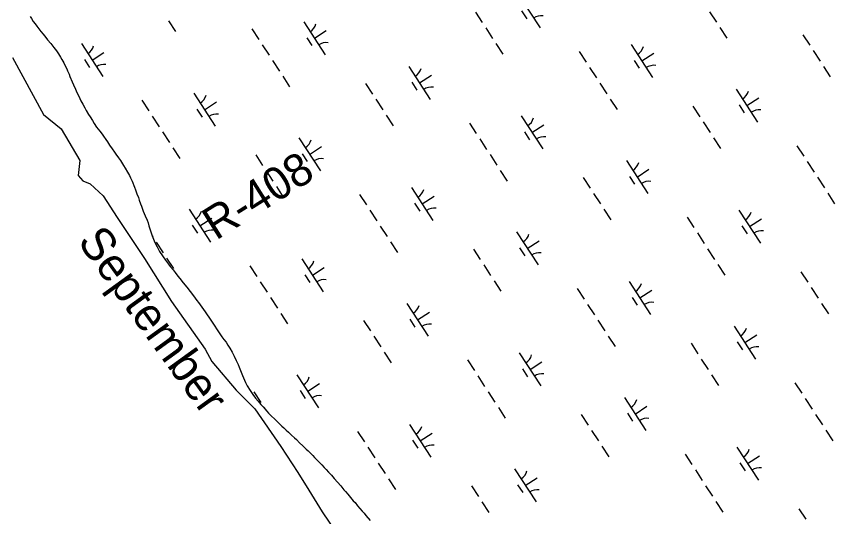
# Model space of a CAD drawing. Extents: x 3953924 to 3974542, y 193747 to 216192.
# Drawn here: x 3964702 to 3965741, y 203866 to 204501 of the extents above; entities that cross this region are included whole.
import ezdxf

# ---------------------------------------------------------------- set-up
doc = ezdxf.new("R2010")
doc.units = 0
for name, color, linetype in [('V-RIVR-EDGE', 7, 'Continuous'), ('V-RIVR-IDEN', 7, 'Continuous'), ('V-RIVR-RANG-IDEN', 7, 'Continuous'), ('V-WETL-SWMP', 7, 'Continuous')]:
    doc.layers.add(name, color=color, linetype=linetype)

msp = doc.modelspace()

# ---------------------------------------------------------------- linework, layer by layer
at = {"layer": 'V-RIVR-EDGE'}
msp.add_lwpolyline([(3964697.2, 204448.9), (3964736.3, 204376.5), (3964758.9, 204358.6), (3964782.7, 204318.3), (3964780.3, 204299.3), (3964786.2, 204292.2), (3964795.7, 204288.6), (3964812.3, 204273.2), (3964830.1, 204245.9), (3964864.6, 204193.6), (3964899, 204139), (3964941.7, 204078.5), (3964950, 204063), (3964980.9, 204026.2), (3965004.7, 204002.5), (3965037.9, 203955), (3965059.3, 203921.8), (3965073.5, 203899.2), (3965090.1, 203871.9), (3965116.3, 203833.9)], dxfattribs=at)
at = {"layer": 'V-WETL-SWMP'}
for p, q in [((3965339.6, 204528.5), (3965366.9, 204486.6)), ((3964719.4, 204501.3), (3964721.3, 204498.4)), ((3965284.8, 204506.8), (3965293.6, 204493.4)), ((3965343.5, 204508.3), (3965350, 204498.3)), ((3965582.2, 204507.1), (3965591, 204493.7)), ((3964721.3, 204498.4), (3964723.4, 204494.9)), ((3964723.4, 204494.9), (3964725.7, 204491.7)), ((3964725.7, 204491.7), (3964727.9, 204488.9)), ((3964895.3, 204495.4), (3964904, 204482)), ((3965066.8, 204494.3), (3965094, 204452.4)), ((3964727.9, 204488.9), (3964730.6, 204485.6)), ((3964730.6, 204485.6), (3964733.2, 204482.2)), ((3964733.2, 204482.2), (3964736, 204478.5)), ((3965000.9, 204485.4), (3965009.7, 204472)), ((3965080.4, 204473.4), (3965095.5, 204483.2)), ((3965297.9, 204486.7), (3965306.7, 204473.3)), ((3965595.3, 204487), (3965604.1, 204473.6)), ((3964736, 204478.5), (3964739.4, 204474.3)), ((3964739.4, 204474.3), (3964741.7, 204471.6)), ((3964741.7, 204471.6), (3964745.6, 204466.8)), ((3965070.7, 204474.2), (3965077.2, 204464.2)), ((3965700.5, 204478), (3965709.3, 204464.6)), ((3964745.6, 204466.8), (3964749.5, 204461.7)), ((3964749.5, 204461.7), (3964752.8, 204457.3)), ((3964784.5, 204466.6), (3964811.7, 204424.7)), ((3965014, 204465.3), (3965022.8, 204451.9)), ((3965311, 204466.6), (3965319.7, 204453.2)), ((3965482.5, 204465.5), (3965509.8, 204423.6)), ((3964752.8, 204457.3), (3964755.5, 204453.5)), ((3964755.5, 204453.5), (3964758.1, 204449.3)), ((3964758.1, 204449.3), (3964759.8, 204446.5)), ((3964798.1, 204445.6), (3964813.2, 204455.4)), ((3965416.7, 204456.6), (3965425.4, 204443.2)), ((3965496.1, 204444.6), (3965511.2, 204454.4)), ((3965713.6, 204457.8), (3965722.4, 204444.4)), ((3964759.8, 204446.5), (3964762.2, 204442.1)), ((3964762.2, 204442.1), (3964763.7, 204439.1)), ((3964763.7, 204439.1), (3964765.9, 204434.8)), ((3964788.4, 204446.4), (3964794.9, 204436.4)), ((3965027.1, 204445.2), (3965035.9, 204431.8)), ((3965486.4, 204445.4), (3965492.9, 204435.3)), ((3964765.9, 204434.8), (3964767.1, 204432)), ((3964767.1, 204432), (3964768.9, 204427.8)), ((3965200.2, 204437.7), (3965227.5, 204395.8)), ((3965429.7, 204436.5), (3965438.5, 204423.1)), ((3965726.7, 204437.7), (3965735.5, 204424.3)), ((3964768.9, 204427.8), (3964770.1, 204425)), ((3964770.1, 204425), (3964772.8, 204418.3)), ((3964772.8, 204418.3), (3964774.6, 204414.2)), ((3965040.2, 204425.1), (3965048.9, 204411.7)), ((3965204.1, 204417.6), (3965210.6, 204407.5)), ((3965213.8, 204416.8), (3965228.9, 204426.6)), ((3964774.6, 204414.2), (3964777, 204408.7)), ((3964777, 204408.7), (3964778.9, 204404.4)), ((3965145.4, 204416), (3965154.2, 204402.6)), ((3965442.8, 204416.4), (3965451.6, 204402.9)), ((3965615.9, 204408.9), (3965643.2, 204367)), ((3964778.9, 204404.4), (3964780.4, 204401.4)), ((3964780.4, 204401.4), (3964782.5, 204396.9)), ((3964782.5, 204396.9), (3964784, 204394)), ((3964927.4, 204403.6), (3964954.6, 204361.7)), ((3965629.5, 204387.9), (3965644.6, 204397.8)), ((3964784, 204394), (3964786.4, 204389.7)), ((3964786.4, 204389.7), (3964788.8, 204385.2)), ((3964861.5, 204394.7), (3964870.3, 204381.3)), ((3964941, 204382.6), (3964956.1, 204392.5)), ((3965158.5, 204395.9), (3965167.2, 204382.5)), ((3965455.9, 204396.2), (3965464.7, 204382.8)), ((3965561.1, 204387.2), (3965569.9, 204373.8)), ((3965619.8, 204388.8), (3965626.3, 204378.7)), ((3964788.8, 204385.2), (3964790.7, 204381.9)), ((3964790.7, 204381.9), (3964793.7, 204376.8)), ((3964793.7, 204376.8), (3964795.5, 204373.8)), ((3964931.3, 204383.5), (3964937.8, 204373.4)), ((3964795.5, 204373.8), (3964798.6, 204368.8)), ((3964798.6, 204368.8), (3964800.7, 204365.3)), ((3964874.6, 204374.6), (3964883.4, 204361.1)), ((3965171.6, 204375.8), (3965180.3, 204362.4)), ((3965277.2, 204365.8), (3965286, 204352.4)), ((3965343.1, 204374.8), (3965370.3, 204332.9)), ((3965574.2, 204367.1), (3965583, 204353.7)), ((3964800.7, 204365.3), (3964803.8, 204360.6)), ((3964803.8, 204360.6), (3964805.9, 204357.8)), ((3964805.9, 204357.8), (3964808, 204355.3)), ((3964808, 204355.3), (3964810.9, 204351.7)), ((3965356.7, 204353.8), (3965371.8, 204363.6)), ((3964810.9, 204351.7), (3964812.6, 204349)), ((3964812.6, 204349), (3964815.5, 204345)), ((3964815.5, 204345), (3964817.7, 204341.7)), ((3964887.7, 204354.4), (3964896.4, 204341)), ((3965060.8, 204347), (3965088.1, 204305.1)), ((3965290.3, 204345.7), (3965299.1, 204332.3)), ((3965347, 204354.6), (3965353.5, 204344.6)), ((3965587.3, 204347), (3965596.1, 204333.6)), ((3964817.7, 204341.7), (3964820.3, 204337.7)), ((3964820.3, 204337.7), (3964823.5, 204333.1)), ((3965074.4, 204326), (3965089.5, 204335.8)), ((3965693, 204337), (3965701.7, 204323.6)), ((3964823.5, 204333.1), (3964826.4, 204328.9)), ((3964826.4, 204328.9), (3964828.2, 204326.3)), ((3964828.2, 204326.3), (3964831.5, 204321.7)), ((3964900.8, 204334.3), (3964909.5, 204320.9)), ((3965006, 204325.3), (3965014.7, 204311.9)), ((3965064.7, 204326.8), (3965071.2, 204316.8)), ((3965303.4, 204325.6), (3965312.2, 204312.2)), ((3964831.5, 204321.7), (3964834.2, 204318)), ((3964834.2, 204318), (3964838.2, 204312)), ((3965476.5, 204318.2), (3965503.8, 204276.2)), ((3965706.1, 204316.9), (3965714.8, 204303.5)), ((3964838.2, 204312), (3964840.2, 204308.4)), ((3964840.2, 204308.4), (3964843.1, 204303.3)), ((3964843.1, 204303.3), (3964845.5, 204299)), ((3965019.1, 204305.2), (3965027.8, 204291.8)), ((3965316.5, 204305.5), (3965325.3, 204292.1)), ((3965490.1, 204297.2), (3965505.2, 204307)), ((3964845.5, 204299), (3964846.9, 204296.3)), ((3964846.9, 204296.3), (3964848.9, 204291.8)), ((3965421.7, 204296.5), (3965430.5, 204283.1)), ((3965480.4, 204298), (3965486.9, 204288)), ((3965719.2, 204296.8), (3965727.9, 204283.4)), ((3964848.9, 204291.8), (3964852, 204284.1)), ((3964852, 204284.1), (3964853.1, 204280.7)), ((3965032.2, 204285.1), (3965040.9, 204271.7)), ((3965203.7, 204284), (3965230.9, 204242.1)), ((3964853.1, 204280.7), (3964855.1, 204275.9)), ((3964855.1, 204275.9), (3964856.9, 204271)), ((3965137.8, 204275.1), (3965146.6, 204261.7)), ((3965217.3, 204263.1), (3965232.4, 204272.9)), ((3965434.8, 204276.4), (3965443.6, 204263)), ((3965732.2, 204276.7), (3965741, 204263.3)), ((3964856.9, 204271), (3964858, 204267.9)), ((3964858, 204267.9), (3964859.8, 204263)), ((3964859.8, 204263), (3964860.9, 204260)), ((3965207.6, 204263.9), (3965214.1, 204253.8)), ((3964860.9, 204260), (3964862.8, 204254)), ((3964862.8, 204254), (3964865.7, 204247.8)), ((3964921.4, 204256.2), (3964948.6, 204214.3)), ((3965150.9, 204255), (3965159.7, 204241.6)), ((3965447.9, 204256.2), (3965456.7, 204242.8)), ((3965619.4, 204255.2), (3965646.7, 204213.3)), ((3964865.7, 204247.8), (3964868.2, 204242.4)), ((3964868.2, 204242.4), (3964869.2, 204239.1)), ((3964935, 204235.3), (3964950.1, 204245.1)), ((3965553.6, 204246.3), (3965562.3, 204232.9)), ((3965633, 204234.2), (3965648.1, 204244.1)), ((3964869.2, 204239.1), (3964870.4, 204235.1)), ((3964870.4, 204235.1), (3964871.9, 204230.3)), ((3964925.3, 204236.1), (3964931.8, 204226)), ((3965164, 204234.9), (3965172.8, 204221.5)), ((3965623.3, 204235.1), (3965629.8, 204225)), ((3964871.9, 204230.3), (3964872.9, 204227.4)), ((3964872.9, 204227.4), (3964874.4, 204222.6)), ((3964874.4, 204222.6), (3964876.1, 204218.4)), ((3964874.4, 204222.5), (3964875.3, 204221.2)), ((3965337.1, 204227.4), (3965364.4, 204185.5)), ((3965566.7, 204226.1), (3965575.4, 204212.7)), ((3964876.1, 204218.4), (3964877.9, 204214.1)), ((3964877.9, 204214.1), (3964880.6, 204208.5)), ((3964879.7, 204214.4), (3964888.4, 204201)), ((3965177.1, 204214.7), (3965185.9, 204201.3)), ((3965350.7, 204206.5), (3965365.8, 204216.3)), ((3964880.6, 204208.5), (3964883.8, 204202.7)), ((3964883.8, 204202.7), (3964887.5, 204197.1)), ((3965282.3, 204205.7), (3965291.1, 204192.3)), ((3965341, 204207.3), (3965347.5, 204197.2)), ((3965579.7, 204206), (3965588.5, 204192.6)), ((3964887.5, 204197.1), (3964891.4, 204191.7)), ((3964891.4, 204191.7), (3964895.2, 204186.4)), ((3964892.8, 204194.3), (3964901.5, 204180.9)), ((3965064.3, 204193.3), (3965091.5, 204151.4)), ((3964895.2, 204186.4), (3964897.4, 204183.5)), ((3964897.4, 204183.5), (3964901, 204179.1)), ((3964901, 204179.1), (3964903.5, 204175.7)), ((3964998.4, 204184.3), (3965007.2, 204170.9)), ((3965077.9, 204172.3), (3965093, 204182.1)), ((3965295.4, 204185.6), (3965304.2, 204172.2)), ((3965592.8, 204185.9), (3965601.6, 204172.5)), ((3964903.5, 204175.7), (3964907.2, 204171.2)), ((3964907.2, 204171.2), (3964909.6, 204168.2)), ((3965068.2, 204173.1), (3965074.7, 204163.1)), ((3965698, 204176.9), (3965706.8, 204163.5)), ((3964909.6, 204168.2), (3964913.8, 204162.8)), ((3964913.8, 204162.8), (3964918.3, 204157.3)), ((3965011.5, 204164.2), (3965020.3, 204150.8)), ((3965308.5, 204165.5), (3965317.2, 204152.1)), ((3965480, 204164.4), (3965507.3, 204122.5)), ((3964918.3, 204157.3), (3964922.5, 204151.7)), ((3964922.5, 204151.7), (3964927, 204146.1)), ((3965414.2, 204155.5), (3965422.9, 204142.1)), ((3965493.6, 204143.5), (3965508.7, 204153.3)), ((3965711.1, 204156.8), (3965719.9, 204143.4)), ((3964927, 204146.1), (3964931.2, 204140.2)), ((3964931.2, 204140.2), (3964933.1, 204137.8)), ((3964933.1, 204137.8), (3964937.4, 204131.9)), ((3965024.6, 204144.1), (3965033.4, 204130.7)), ((3965483.9, 204144.3), (3965490.4, 204134.3)), ((3964937.4, 204131.9), (3964941.8, 204125.9)), ((3965197.7, 204136.7), (3965225, 204094.8)), ((3965427.2, 204135.4), (3965436, 204122)), ((3965724.2, 204136.7), (3965733, 204123.3)), ((3964941.8, 204125.9), (3964944.3, 204122)), ((3964944.3, 204122), (3964946.2, 204119.2)), ((3964946.2, 204119.2), (3964948.9, 204115.4)), ((3965037.7, 204124), (3965046.4, 204110.6)), ((3965201.6, 204116.5), (3965208.1, 204106.5)), ((3965211.3, 204115.7), (3965226.4, 204125.5)), ((3964948.9, 204115.4), (3964953.2, 204109)), ((3964953.2, 204109), (3964957.1, 204102.9)), ((3965142.9, 204115), (3965151.7, 204101.6)), ((3965440.3, 204115.3), (3965449.1, 204101.9)), ((3965613.4, 204107.8), (3965640.7, 204065.9)), ((3964957.1, 204102.9), (3964960.5, 204098)), ((3964960.5, 204098), (3964963, 204094.2)), ((3965627, 204086.9), (3965642.1, 204096.7)), ((3964963, 204094.2), (3964965.6, 204090.9)), ((3964965.6, 204090.9), (3964968.5, 204087.2)), ((3964968.5, 204087.2), (3964970.7, 204083.5)), ((3965156, 204094.9), (3965164.7, 204081.5)), ((3965453.4, 204095.2), (3965462.2, 204081.8)), ((3965558.6, 204086.2), (3965567.4, 204072.7)), ((3965617.3, 204087.7), (3965623.8, 204077.6)), ((3964970.7, 204083.5), (3964972.9, 204079.6)), ((3964972.9, 204079.6), (3964976, 204074.5)), ((3965169.1, 204074.8), (3965177.8, 204061.3)), ((3964976, 204074.5), (3964978.6, 204069.4)), ((3964978.6, 204069.4), (3964981.1, 204064.3)), ((3965274.8, 204064.8), (3965283.5, 204051.4)), ((3965340.6, 204073.7), (3965367.8, 204031.8)), ((3965571.7, 204066), (3965580.5, 204052.6)), ((3964981.1, 204064.3), (3964983.6, 204059.1)), ((3964983.6, 204059.1), (3964985, 204055.5)), ((3964985, 204055.5), (3964987.5, 204049.2)), ((3965354.2, 204052.8), (3965369.3, 204062.6)), ((3964987.5, 204049.2), (3964989.1, 204045.1)), ((3964989.1, 204045.1), (3964992.9, 204036.3)), ((3965058.3, 204045.9), (3965085.6, 204004)), ((3965287.8, 204044.7), (3965296.6, 204031.2)), ((3965344.5, 204053.6), (3965351, 204043.5)), ((3965584.8, 204045.9), (3965593.6, 204032.5)), ((3964992.9, 204036.3), (3964995, 204032)), ((3965071.9, 204025), (3965087, 204034.8)), ((3965690.5, 204035.9), (3965699.2, 204022.5)), ((3964995, 204032), (3964998.9, 204025.9)), ((3964998.9, 204025.9), (3965002.3, 204020.7)), ((3965003.5, 204024.2), (3965012.3, 204010.8)), ((3965062.2, 204025.8), (3965068.7, 204015.7)), ((3965300.9, 204024.5), (3965309.7, 204011.1)), ((3965002.3, 204020.7), (3965005.7, 204016.4)), ((3965005.7, 204016.4), (3965008.9, 204012.5)), ((3965008.9, 204012.5), (3965012.4, 204008.3)), ((3965474, 204017.1), (3965501.3, 203975.2)), ((3965703.6, 204015.8), (3965712.3, 204002.4)), ((3965012.4, 204008.3), (3965015.2, 204005.3)), ((3965015.2, 204005.3), (3965017.5, 204002.8)), ((3965016.6, 204004.1), (3965017.4, 204002.9)), ((3965017.5, 204002.8), (3965020, 203999.9)), ((3965314, 204004.4), (3965322.8, 203991)), ((3965487.6, 203996.1), (3965502.7, 204006)), ((3965020, 203999.9), (3965022.3, 203997.4)), ((3965022.3, 203997.4), (3965033.4, 203986.1)), ((3965419.2, 203995.4), (3965428, 203982)), ((3965477.9, 203997), (3965484.4, 203986.9)), ((3965716.7, 203995.7), (3965725.4, 203982.3)), ((3965033.4, 203986.1), (3965036.8, 203982.8)), ((3965036.8, 203982.8), (3965039.2, 203980.6)), ((3965201.2, 203983), (3965228.4, 203941.1)), ((3965039.2, 203980.6), (3965041.7, 203978.4)), ((3965041.7, 203978.4), (3965044.4, 203975.8)), ((3965044.4, 203975.8), (3965047.5, 203972.9)), ((3965047.5, 203972.9), (3965051.3, 203969.4)), ((3965135.3, 203974), (3965144.1, 203960.6)), ((3965214.8, 203962), (3965229.9, 203971.8)), ((3965432.3, 203975.3), (3965441.1, 203961.9)), ((3965729.7, 203975.6), (3965738.5, 203962.2)), ((3965051.3, 203969.4), (3965055.2, 203965.7)), ((3965055.2, 203965.7), (3965057.6, 203963.6)), ((3965057.6, 203963.6), (3965061.7, 203959.6)), ((3965205.1, 203962.8), (3965211.6, 203952.8)), ((3965061.7, 203959.6), (3965065.7, 203955.8)), ((3965065.7, 203955.8), (3965070, 203951.6)), ((3965070, 203951.6), (3965072.5, 203949.4)), ((3965148.4, 203953.9), (3965157.2, 203940.5)), ((3965445.4, 203955.2), (3965454.2, 203941.8)), ((3965616.9, 203954.1), (3965644.2, 203912.2)), ((3965072.5, 203949.4), (3965078.3, 203943.5)), ((3965078.3, 203943.5), (3965080.7, 203941)), ((3965080.7, 203941), (3965083.1, 203938.5)), ((3965551.1, 203945.2), (3965559.8, 203931.8)), ((3965630.5, 203933.2), (3965645.6, 203943)), ((3965083.1, 203938.5), (3965086, 203935.5)), ((3965086, 203935.5), (3965090, 203931.7)), ((3965090, 203931.7), (3965093, 203928.3)), ((3965161.5, 203933.8), (3965170.3, 203920.4)), ((3965620.8, 203934), (3965627.3, 203923.9)), ((3965093, 203928.3), (3965095.4, 203925.7)), ((3965095.4, 203925.7), (3965098.5, 203922.2)), ((3965098.5, 203922.2), (3965102.1, 203918.3)), ((3965334.6, 203926.3), (3965361.9, 203884.4)), ((3965564.2, 203925.1), (3965572.9, 203911.7)), ((3965102.1, 203918.3), (3965105.7, 203914.2)), ((3965105.7, 203914.2), (3965109.8, 203909.5)), ((3965109.8, 203909.5), (3965113.9, 203904.8)), ((3965174.6, 203913.7), (3965183.4, 203900.3)), ((3965348.2, 203905.4), (3965363.3, 203915.2)), ((3965113.9, 203904.8), (3965118, 203900)), ((3965118, 203900), (3965120.1, 203897.6)), ((3965279.8, 203904.7), (3965288.6, 203891.3)), ((3965338.5, 203906.2), (3965345, 203896.2)), ((3965577.2, 203905), (3965586, 203891.6)), ((3965120.1, 203897.6), (3965123, 203894.2)), ((3965123, 203894.2), (3965126.4, 203890.2)), ((3965126.4, 203890.2), (3965129.8, 203885.9)), ((3965129.8, 203885.9), (3965132, 203883.5)), ((3965132, 203883.5), (3965135.1, 203879.5)), ((3965135.1, 203879.5), (3965138.3, 203876)), ((3965292.9, 203884.6), (3965301.7, 203871.1)), ((3965590.3, 203884.9), (3965599.1, 203871.4)), ((3965138.3, 203876), (3965141, 203872.6)), ((3965141, 203872.6), (3965143.6, 203870)), ((3965143.6, 203870), (3965145.8, 203867)), ((3965145.8, 203867), (3965151.1, 203860.9)), ((3965695.5, 203875.8), (3965704.3, 203862.4))]:
    msp.add_line(p, q, dxfattribs=at)
for centre, start, end in [((3965368.5, 204484.5), 82.2901, 123.8337), ((3965065.5, 204496.7), 302.2901, 343.8338), ((3964783.2, 204468.9), 302.2901, 343.8338), ((3965095.7, 204450.4), 82.2901, 123.8337), ((3965481.2, 204467.8), 302.2901, 343.8338), ((3964813.4, 204422.6), 82.2901, 123.8337), ((3965511.4, 204421.5), 82.2901, 123.8337), ((3965198.9, 204440.1), 302.2901, 343.8338), ((3965229.1, 204393.8), 82.2901, 123.8337), ((3964926.1, 204405.9), 302.2901, 343.8338), ((3965614.7, 204411.2), 302.2901, 343.8338), ((3964956.3, 204359.6), 82.2901, 123.8337), ((3965644.8, 204364.9), 82.2901, 123.8337), ((3965341.8, 204377.1), 302.2901, 343.8338), ((3965372, 204330.8), 82.2901, 123.8337), ((3965059.5, 204349.3), 302.2901, 343.8338), ((3965089.7, 204303), 82.2901, 123.8337), ((3965475.3, 204320.5), 302.2901, 343.8338), ((3965505.4, 204274.2), 82.2901, 123.8337), ((3965202.4, 204286.3), 302.2901, 343.8338), ((3964920.1, 204258.6), 302.2901, 343.8338), ((3965232.6, 204240.1), 82.2901, 123.8337), ((3965618.1, 204257.5), 302.2901, 343.8338), ((3964950.3, 204212.3), 82.2901, 123.8337), ((3965335.9, 204229.7), 302.2901, 343.8338), ((3965648.3, 204211.2), 82.2901, 123.8337), ((3965366, 204183.4), 82.2901, 123.8337), ((3965063, 204195.6), 302.2901, 343.8338), ((3965093.2, 204149.3), 82.2901, 123.8337), ((3965478.7, 204166.8), 302.2901, 343.8338), ((3965508.9, 204120.5), 82.2901, 123.8337), ((3965196.5, 204139), 302.2901, 343.8338), ((3965226.6, 204092.7), 82.2901, 123.8337), ((3965612.2, 204110.2), 302.2901, 343.8338), ((3965642.3, 204063.9), 82.2901, 123.8337), ((3965339.3, 204076), 302.2901, 343.8338), ((3965369.5, 204029.7), 82.2901, 123.8337), ((3965057, 204048.2), 302.2901, 343.8338), ((3965087.2, 204001.9), 82.2901, 123.8337), ((3965472.8, 204019.4), 302.2901, 343.8338), ((3965502.9, 203973.1), 82.2901, 123.8337), ((3965199.9, 203985.3), 302.2901, 343.8338), ((3965230.1, 203939), 82.2901, 123.8337), ((3965615.7, 203956.5), 302.2901, 343.8338), ((3965333.4, 203928.7), 302.2901, 343.8338), ((3965645.8, 203910.2), 82.2901, 123.8337), ((3965363.5, 203882.4), 82.2901, 123.8337)]:
    msp.add_arc(centre, 17.6, start, end, dxfattribs=at)

# ---------------------------------------------------------------- texts
at = {"layer": 'V-RIVR-IDEN'}
msp.add_text('September', height=42, rotation=305.8982, dxfattribs=at).set_placement((3964778.7, 204215.1))
at = {"layer": 'V-RIVR-RANG-IDEN'}
msp.add_text('R-408  ', height=41.5, rotation=32.1876, dxfattribs=at).set_placement((3964955.4, 204216.1))

doc.saveas('drawing.dxf')
